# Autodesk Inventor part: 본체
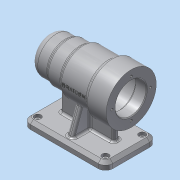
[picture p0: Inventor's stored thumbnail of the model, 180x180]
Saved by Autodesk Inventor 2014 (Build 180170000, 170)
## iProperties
Created: 2016-06
Part Number: 본체
Material: 알루미늄 6061
Document SubType Name: Modeling
Designer: dgall
Density: 2.71 g/cm^3
Appearance: 알루미늄 - 평지
Mass: 672.417 g
Surface Area: 647.545 cm^2
Volume: 248.124 cm^3
Author: dgall
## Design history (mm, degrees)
sketch "스케치1"
  geometry: L1 (-56, 0)-(56, 0); L2 (-56, 0)-(-56, 25); L3 (-56, 25)-(-31, 25); L4 (-31, 25)-(-31, 27); L5 (-31, 27)-(-11, 27); L6 (-11, 27)-(-11, 30); L7 (-11, 30)-(28, 30); L8 (28, 30)-(28, 34); L9 (28, 34)-(56, 34); L10 (56, 34)-(56, 0); 2 further points
  constraints: 20 end point, 6 parallel, 2 vertical, 1 coincident, 1 horizontal, 1 midpoint, 1 perpendicular
  dimensions: "d0" = 112 distance of L1.start L1.end; "d1" = 25 distance of L2.end L3.end; "d3" = 45 distance between parallel lines of L6 L2; "d4" = 84 distance between parallel lines of L8 L2; "d6" = 50 diameter of L3 L1; "d7" = 54 diameter of L5 L1; "d8" = 60 diameter of L7 L1; "d9" = 68 diameter of L9 L1
revolve "회전1" sketch "스케치1" stored, may be unused: angle "d10" = 90 deg
sketch "스케치2"
  geometry: L1 (-56, -25)-(-56, 25) reference; L2 (56, -34)-(56, 34) reference; L3 (-56, 0)-(56, 0); L4 (-50, 0)-(-50, 10.5); L5 (-50, 10.5)-(-47, 10.5); L6 (-47, 10.5)-(-47, 16); L7 (-47, 16)-(-43, 16); L8 (-43, 16)-(-43, 17.5); L9 (-43, 17.5)-(-25, 17.5); L10 (-25, 17.5)-(-25, 21); L11 (-25, 21)-(-13, 21); L12 (-13, 21)-(-13, 24); L13 (-13, 24)-(41, 24); L14 (41, 24)-(41, 21); L15 (41, 21)-(56, 21); 1 further point
  constraints: 26 end point, 6 parallel, 4 perpendicular, 2 midpoint, 2 point on line, 1 horizontal, 1 vertical
  dimensions: "d11" = 3 distance of L4.end L5.end; "d12" = 4 distance of L6.end L7.end; "d13" = 18 distance of L8.end L9.end; "d14" = 12 distance of L10.end L11.end; "d15" = 54 distance of L12.end L13.end; "d16" = 15 distance of L14.end L15.end; "d18" = 21 diameter of L5 L3; "d19" = 32 diameter of L7 L3; "d20" = 35 diameter of L9 L3; "d21" = 42 diameter of L11 L3; "d22" = 48 diameter of L13 L3; "d23" = 42 diameter of L15 L3
revolve "회전2" sketch "스케치2" stored, may be unused: angle "d24" = 90 deg
fillet "모깎기1" dims "d25" = 10
fillet "모깎기2" dims "d26" = 3
fillet "모깎기3" dims "d27" = 3
fillet "모깎기4" dims "d28" = 0.3
chamfer "모따기1" distance "d30" = 1; stored, may be unused: second distance "d31" = 2, angle "d32" = 45 deg
sketch "스케치3"
  geometry: C1 r 34 at (0, 0) reference; 1 further point
  constraints: 1 vertical alignment
  dimensions: "d33" = 26 distance of point (0, 26) C1.centre
hole "구멍1" sketch "스케치3" at (0, 26) diameter "d34" = 3.242; stored, may be unused: countersink angle "d38" = 90 deg, drill point angle "d40" = 118 deg; dims "d35" = 8, "d36" = 4, "d37" = 2, "d39" = 11
node "작업 평면1"
sketch "스케치4"
  geometry: L1 (47.5, -34)-(47.5, 34) reference; 2 further points
  constraints: 1 horizontal alignment, 1 other
  dimensions: "d44" = 48 distance from line of L1 point (-0.5, 0)
feature "엠보싱1" sketch "스케치4" dims "d45" = 0.5, "d46" = 0
node "작업 평면2"
sketch "스케치5"
  geometry: L1 (-56, 35)-(56, 35); L2 (56, 35)-(56, -35); L3 (56, -35)-(-56, -35); L4 (-56, -35)-(-56, 35); 3 further points
  constraints: 8 end point, 2 midpoint, 2 parallel, 1 horizontal, 1 horizontal alignment, 1 perpendicular, 1 vertical alignment
  dimensions: "d48" = 112 distance of L1.start L1.end; "d49" = 70 distance of L3.end L1.start
extrude "돌출1" join sketch "스케치5" distance "d50" = 10; taper "d51" = 0 deg
fillet "모깎기6" dims "d52" = 10
chamfer "모따기2" distance "d53" = 4; stored, may be unused: second distance "d54" = 2, angle "d55" = 45 deg
hole "구멍2" diameter "d58" = 5; stored, may be unused: countersink angle "d62" = 90 deg, drill point angle "d64" = 0 deg; dims "d56" = 10, "d57" = 10, "d59" = 8, "d60" = 9, "d61" = 4, "d63" = 11
sketch "스케치6"
  geometry: L1 (-15.509, -25.68)-(-28, -60); L2 (-35, -70)-(-35, -64) reference; L3 (-25, -70)-(-35, -70) reference; L4 (-29.5, -60)-(-20.5, -60) reference; L5 (-25, -60)-(25, -60) reference; L6 (0, -30)-(0, -60); L7 (15.509, -25.68)-(28, -60); L8 (-28, -60)-(28, -60); A1 r 30 centre (0, 0) between (-15.509, -25.68) and (0, -30) reference; A2 r 30 centre (0, 0) between (-15.509, -25.68) and (15.509, -25.68); 1 further point
  constraints: 8 end point, 6 point on circle, 2 point on line, 2 symmetric about line, 1 centre point, 1 collinear, 1 midpoint, 1 vertical
  dimensions: "d65" = 7 distance from line of L1.end L2; "d66" = 110 deg angle of L1 L3
extrude "돌출2" join sketch "스케치6" stored distance "d67" = 8; taper "d68" = 0 deg
sketch "스케치7"
  geometry: L1 (-36, 4)-(36, 4); L2 (36, 4)-(36, -4); L3 (36, -4)-(-36, -4); L4 (-36, -4)-(-36, 4); L5 (-56, 25)-(-56, -25) reference; 3 further points
  constraints: 8 end point, 2 midpoint, 2 parallel, 1 horizontal, 1 horizontal alignment, 1 perpendicular, 1 vertical alignment
  dimensions: "d69" = 8 distance of L3.end L1.start; "d70" = 20 distance between parallel lines of L4 L5
extrude "돌출3" join sketch "스케치7" stored distance "d71" = 8; taper "d72" = 0 deg
fillet "모깎기7" dims "d73" = 3
fillet "모깎기8" dims "d74" = 3
fillet "모깎기9" dims "d75" = 3
fillet "모깎기10" dims "d76" = 3
fillet "모깎기11" dims "d77" = 3
fillet "모깎기12" dims "d78" = 3
node "솔리드1"
pattern_circular "원형 패턴1" dims angle "d42" = 360 deg
mirror "대칭1"
mirror "대칭2"
